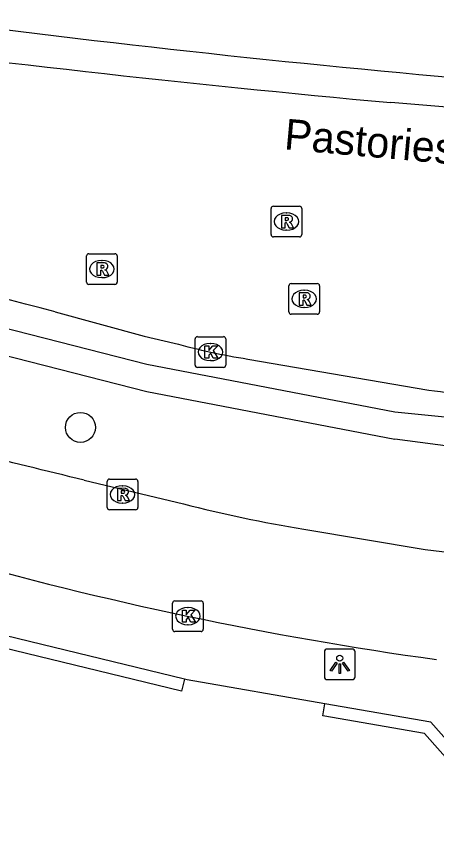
# Model space of a CAD drawing. Extents: x 160861 to 161308, y 384024 to 384878.
# Drawn here: x 161083.27 to 161096.95, y 384841.88 to 384868.78 of the extents above; entities that cross this region are included whole.
import ezdxf

# ---------------------------------------------------------------- set-up
doc = ezdxf.new("R2010")
doc.units = 0
for name, color, linetype in [('IMGEO_Boom', 7, 'Continuous'), ('IMGEO_Haag', 7, 'Continuous'), ('IMGEO_Hek', 7, 'Continuous'), ('IMGEO_Kolk', 7, 'Continuous'), ('IMGEO_Lichtpunt', 7, 'Continuous'), ('IMGEO_Openbare_ruimte_label', 7, 'Continuous'), ('IMGEO_Rijbaan_lokaal_gesloten', 7, 'Continuous'), ('IMGEO_Rijbaan_regionaal_gesloten', 7, 'Continuous'), ('IMGEO_Rioolput', 7, 'Continuous'), ('IMGEO_Voetpad_open', 7, 'Continuous')]:
    doc.layers.add(name, color=color, linetype=linetype)

msp = doc.modelspace()

# ---------------------------------------------------------------- linework, layer by layer
at = {"layer": 'IMGEO_Boom'}
msp.add_circle((161085.352, 384855.4), 0.489, dxfattribs=at)
at = {"layer": 'IMGEO_Haag'}
for points in [[(161088.737, 384847.203), (161088.643, 384846.814), (161078.539, 384849.258), (161075.222, 384849.959), (161068.388, 384851.138)], [(161131.313, 384846.712), (161129.022, 384846.468), (161124.766, 384845.773), (161120.159, 384844.667), (161118.797, 384843.061), (161117.09, 384841.916), (161113.104, 384841.881), (161098.682, 384843.036), (161096.561, 384845.428), (161093.247, 384846.005), (161093.316, 384846.399)]]:
    msp.add_lwpolyline(points, dxfattribs=at)
at = {"layer": 'IMGEO_Hek'}
for points in [[(160981.991, 384864.071), (160981.991, 384864.963), (160990.538, 384865.942), (161000.837, 384866.621), (161011.863, 384866.872), (161023.361, 384866.572), (161034.743, 384865.752), (161045.874, 384864.511), (161070.2, 384861.176), (161078.924, 384859.65), (161087.515, 384857.461), (161095.594, 384855.909)], [(160981.991, 384864.071), (160990.538, 384865.05), (161000.837, 384865.729), (161011.863, 384865.98), (161023.361, 384865.68), (161034.743, 384864.86), (161045.874, 384863.619), (161070.2, 384860.284), (161078.924, 384858.758), (161087.515, 384856.569), (161095.594, 384855.017)], [(161095.594, 384855.909), (161105.396, 384854.928)], [(161100.043, 384854.427), (161095.594, 384855.017)]]:
    msp.add_lwpolyline(points, dxfattribs=at)
at = {"layer": 'IMGEO_Kolk'}
for p, q in [((161089.16, 384858.354), (161090.012, 384858.354)), ((161089.085, 384857.428), (161089.085, 384858.28)), ((161089.573, 384858.134), (161089.598, 384858.134)), ((161090.086, 384858.28), (161090.086, 384857.428)), ((161089.596, 384857.574), (161089.571, 384857.574)), ((161090.012, 384857.354), (161089.16, 384857.354)), ((161088.426, 384849.751), (161089.278, 384849.751)), ((161088.351, 384848.825), (161088.351, 384849.677)), ((161088.839, 384849.531), (161088.864, 384849.531)), ((161089.352, 384849.677), (161089.352, 384848.825)), ((161088.862, 384848.971), (161088.837, 384848.971)), ((161089.278, 384848.751), (161088.426, 384848.751))]:
    msp.add_line(p, q, dxfattribs=at)
for points in [[(161089.16, 384858.354), (161090.012, 384858.354)], [(161089.085, 384857.428), (161089.085, 384858.28)], [(161089.406, 384858.054), (161089.529, 384858.054), (161089.529, 384857.903), (161089.659, 384858.054), (161089.823, 384858.054), (161089.677, 384857.903), (161089.83, 384857.654), (161089.678, 384857.654), (161089.593, 384857.818), (161089.529, 384857.751), (161089.529, 384857.654), (161089.406, 384857.654), (161089.406, 384858.054)], [(161090.086, 384858.28), (161090.086, 384857.428)], [(161090.012, 384857.354), (161089.16, 384857.354)], [(161088.426, 384849.751), (161089.278, 384849.751)], [(161088.351, 384848.825), (161088.351, 384849.677)], [(161088.672, 384849.451), (161088.795, 384849.451), (161088.795, 384849.3), (161088.925, 384849.451), (161089.089, 384849.451), (161088.943, 384849.3), (161089.096, 384849.051), (161088.944, 384849.051), (161088.859, 384849.215), (161088.795, 384849.148), (161088.795, 384849.051), (161088.672, 384849.051), (161088.672, 384849.451)], [(161089.352, 384849.677), (161089.352, 384848.825)], [(161089.278, 384848.751), (161088.426, 384848.751)]]:
    msp.add_lwpolyline(points, dxfattribs=at)
for centre, start, end in [((161089.162, 384858.278), 91.552, 178.448), ((161089.162, 384858.278), 91.552, 178.448), ((161090.01, 384858.278), 1.552, 88.448), ((161090.01, 384858.278), 1.552, 88.448), ((161089.162, 384857.43), 181.552, 268.448), ((161089.162, 384857.43), 181.552, 268.448), ((161090.01, 384857.43), 271.552, 358.448), ((161090.01, 384857.43), 271.552, 358.448), ((161088.428, 384849.675), 91.552, 178.448), ((161088.428, 384849.675), 91.552, 178.448), ((161089.276, 384849.675), 1.552, 88.448), ((161089.276, 384849.675), 1.552, 88.448), ((161088.428, 384848.827), 181.552, 268.448), ((161088.428, 384848.827), 181.552, 268.448), ((161089.276, 384848.827), 271.552, 358.448), ((161089.276, 384848.827), 271.552, 358.448)]:
    msp.add_arc(centre, 0.0765, start, end, dxfattribs=at)
for centre, major_axis, ratio, start_param, end_param in [((161089.572, 384857.854), (-0.387, 0.002), 0.722429, 4.712389, 7.853982), ((161089.597, 384857.854), (-0.39, 0.002), 0.717154, 1.570796, 4.712389), ((161088.838, 384849.251), (-0.387, 0.002), 0.722429, 4.712389, 7.853982), ((161088.863, 384849.251), (-0.39, 0.002), 0.717154, 1.570796, 4.712389)]:
    msp.add_ellipse(centre, major_axis=major_axis, ratio=ratio, start_param=start_param, end_param=end_param, dxfattribs=at)
at = {"layer": 'IMGEO_Lichtpunt'}
for p, q in [((161093.298, 384848.086), (161093.298, 384847.279)), ((161093.298, 384848.086), (161093.298, 384847.279)), ((161094.2, 384848.181), (161093.392, 384848.181)), ((161094.2, 384848.181), (161093.392, 384848.181)), ((161094.294, 384847.279), (161094.294, 384848.086)), ((161094.294, 384847.279), (161094.294, 384848.086)), ((161093.392, 384847.185), (161094.2, 384847.185)), ((161093.392, 384847.185), (161094.2, 384847.185))]:
    msp.add_line(p, q, dxfattribs=at)
for points in [[(161093.672, 384847.75), (161093.711, 384847.722), (161093.523, 384847.46), (161093.485, 384847.487), (161093.672, 384847.75)], [(161093.774, 384847.702), (161093.821, 384847.702), (161093.821, 384847.38), (161093.774, 384847.38), (161093.774, 384847.702)], [(161093.884, 384847.722), (161093.922, 384847.749), (161094.109, 384847.487), (161094.07, 384847.459), (161093.884, 384847.722)]]:
    msp.add_lwpolyline(points, dxfattribs=at)
msp.add_circle((161093.797, 384847.884), 0.0994, dxfattribs=at)
for centre, start, end in [((161093.392, 384848.086), 90, 180), ((161093.392, 384848.086), 90, 180), ((161094.2, 384848.086), 0, 90), ((161094.2, 384848.086), 0, 90), ((161093.392, 384847.279), 180, 270), ((161093.392, 384847.279), 180, 270), ((161094.2, 384847.279), 270, 0), ((161094.2, 384847.279), 270, 360)]:
    msp.add_arc(centre, 0.0946, start, end, dxfattribs=at)
at = {"layer": 'IMGEO_Rijbaan_lokaal_gesloten'}
for points in [[(161085.474, 384853.678), (161088.702, 384852.908)], [(161092.626, 384852.085), (161096.576, 384851.42), (161097.579, 384851.298)]]:
    msp.add_lwpolyline(points, dxfattribs=at)
for centre, radius, start, end in [((160824.463, 383796.83), 1088.602, 76.127183, 76.531378), ((161099.998, 384897), 45.516, 255.6304, 260.6791), ((161113.478, 384966.524), 119.831, 254.19065, 262.07039)]:
    msp.add_arc(centre, radius, start, end, dxfattribs=at)
at = {"layer": 'IMGEO_Rijbaan_regionaal_gesloten'}
for points in [[(161103.416, 384865.317), (161095.457, 384865.978)], [(161084.524, 384859.161), (161087.422, 384858.375), (161088.402, 384858.146)], [(161090.803, 384857.626), (161096.702, 384856.617)]]:
    msp.add_lwpolyline(points, dxfattribs=at)
for centre, radius, start, end in [((161134.125, 385278.867), 413.695, 262.42605, 265.19774), ((161139.404, 385346.014), 482.044, 262.39283, 264.76917), ((161052.796, 384740.74), 122.598, 75.00108, 82.48577), ((161094.191, 384879.075), 21.715, 254.537, 261.0226), ((161105.571, 384916.995), 61.026, 261.64364, 264.46154)]:
    msp.add_arc(centre, radius, start, end, dxfattribs=at)
at = {"layer": 'IMGEO_Rioolput'}
for p, q in [((161091.634, 384862.604), (161092.486, 384862.604)), ((161091.559, 384861.678), (161091.559, 384862.53)), ((161092.047, 384862.384), (161092.072, 384862.384)), ((161092.56, 384862.53), (161092.56, 384861.678)), ((161092.07, 384861.824), (161092.045, 384861.824)), ((161092.486, 384861.604), (161091.634, 384861.604)), ((161085.624, 384861.057), (161086.476, 384861.057)), ((161085.549, 384860.131), (161085.549, 384860.983)), ((161086.037, 384860.837), (161086.062, 384860.837)), ((161086.55, 384860.983), (161086.55, 384860.131)), ((161086.06, 384860.277), (161086.035, 384860.277)), ((161086.476, 384860.057), (161085.624, 384860.057)), ((161092.139, 384859.159), (161092.139, 384860.011)), ((161092.214, 384860.085), (161093.066, 384860.085)), ((161093.14, 384860.011), (161093.14, 384859.159)), ((161092.627, 384859.865), (161092.652, 384859.865)), ((161092.65, 384859.305), (161092.625, 384859.305)), ((161093.066, 384859.085), (161092.214, 384859.085)), ((161086.22, 384852.79), (161086.22, 384853.642)), ((161086.295, 384853.716), (161087.147, 384853.716)), ((161086.708, 384853.496), (161086.733, 384853.496)), ((161087.221, 384853.642), (161087.221, 384852.79)), ((161086.731, 384852.936), (161086.706, 384852.936)), ((161087.147, 384852.716), (161086.295, 384852.716))]:
    msp.add_line(p, q, dxfattribs=at)
for points in [[(161091.634, 384862.604), (161092.486, 384862.604)], [(161091.559, 384861.678), (161091.559, 384862.53)], [(161092.56, 384862.53), (161092.56, 384861.678)], [(161092.148, 384862.302), (161091.896, 384862.304), (161091.896, 384861.904)], [(161091.896, 384861.904), (161092.02, 384861.904), (161092.02, 384862.066), (161092.031, 384862.066)], [(161092.074, 384862.223), (161092.02, 384862.223), (161092.02, 384862.142)], [(161092.02, 384862.142), (161092.072, 384862.142)], [(161092.078, 384862.037), (161092.149, 384861.904), (161092.289, 384861.904), (161092.224, 384862.03)], [(161092.486, 384861.604), (161091.634, 384861.604)], [(161085.624, 384861.057), (161086.476, 384861.057)], [(161085.549, 384860.131), (161085.549, 384860.983)], [(161086.138, 384860.755), (161085.886, 384860.757), (161085.886, 384860.357)], [(161086.55, 384860.983), (161086.55, 384860.131)], [(161085.886, 384860.357), (161086.01, 384860.357), (161086.01, 384860.519), (161086.021, 384860.519)], [(161086.064, 384860.676), (161086.01, 384860.676), (161086.01, 384860.595)], [(161086.01, 384860.595), (161086.062, 384860.595)], [(161086.068, 384860.49), (161086.139, 384860.357), (161086.279, 384860.357), (161086.214, 384860.483)], [(161086.476, 384860.057), (161085.624, 384860.057)], [(161092.139, 384859.159), (161092.139, 384860.011)], [(161092.214, 384860.085), (161093.066, 384860.085)], [(161093.14, 384860.011), (161093.14, 384859.159)], [(161092.728, 384859.783), (161092.476, 384859.785), (161092.476, 384859.385)], [(161092.654, 384859.704), (161092.6, 384859.704), (161092.6, 384859.623)], [(161092.476, 384859.385), (161092.6, 384859.385), (161092.6, 384859.547), (161092.611, 384859.547)], [(161092.6, 384859.623), (161092.652, 384859.623)], [(161092.658, 384859.518), (161092.729, 384859.385), (161092.869, 384859.385), (161092.804, 384859.511)], [(161093.066, 384859.085), (161092.214, 384859.085)], [(161086.22, 384852.79), (161086.22, 384853.642)], [(161086.295, 384853.716), (161087.147, 384853.716)], [(161087.221, 384853.642), (161087.221, 384852.79)], [(161086.809, 384853.414), (161086.557, 384853.416), (161086.557, 384853.016)], [(161086.735, 384853.335), (161086.681, 384853.335), (161086.681, 384853.254)], [(161086.681, 384853.254), (161086.733, 384853.254)], [(161086.557, 384853.016), (161086.681, 384853.016), (161086.681, 384853.178), (161086.692, 384853.178)], [(161086.739, 384853.149), (161086.81, 384853.016), (161086.95, 384853.016), (161086.885, 384853.142)], [(161087.147, 384852.716), (161086.295, 384852.716)]]:
    msp.add_lwpolyline(points, dxfattribs=at)
for centre, radius, start, end in [((161091.636, 384862.528), 0.0765, 91.552, 178.448), ((161091.636, 384862.528), 0.0765, 91.552, 178.448), ((161092.484, 384862.528), 0.0765, 1.552, 88.448), ((161092.484, 384862.528), 0.0765, 1.552, 88.448), ((161092.03, 384862.013), 0.0533, 26.0293, 88.6989), ((161092.056, 384862.331), 0.19, 274.7715, 282.9687), ((161092.08, 384862.127), 0.0964, 77.0061, 93.1865), ((161092.094, 384862.184), 0.0378, 276.6634, 79.6772), ((161092.147, 384862.192), 0.109, 350.3612, 89.416), ((161092.145, 384862.192), 0.112, 277.5842, 350.9817), ((161092.129, 384861.977), 0.108, 29.5134, 73.7905), ((161091.636, 384861.68), 0.0765, 181.552, 268.448), ((161091.636, 384861.68), 0.0765, 181.552, 268.448), ((161092.484, 384861.68), 0.0765, 271.552, 358.448), ((161092.484, 384861.68), 0.0765, 271.552, 358.448), ((161085.626, 384860.981), 0.0765, 91.552, 178.448), ((161085.626, 384860.981), 0.0765, 91.552, 178.448), ((161086.474, 384860.981), 0.0765, 1.552, 88.448), ((161086.474, 384860.981), 0.0765, 1.552, 88.448), ((161086.137, 384860.645), 0.109, 350.3612, 89.416), ((161086.02, 384860.466), 0.0533, 26.0293, 88.6989), ((161086.046, 384860.784), 0.19, 274.7715, 282.9687), ((161086.07, 384860.58), 0.0964, 77.0061, 93.1865), ((161086.084, 384860.637), 0.0378, 276.6634, 79.6772), ((161086.135, 384860.645), 0.112, 277.5842, 350.9817), ((161086.119, 384860.43), 0.108, 29.5134, 73.7905), ((161085.626, 384860.133), 0.0765, 181.552, 268.448), ((161085.626, 384860.133), 0.0765, 181.552, 268.448), ((161086.474, 384860.133), 0.0765, 271.552, 358.448), ((161086.474, 384860.133), 0.0765, 271.552, 358.448), ((161092.216, 384860.009), 0.0765, 91.552, 178.448), ((161092.216, 384860.009), 0.0765, 91.552, 178.448), ((161093.064, 384860.009), 0.0765, 1.552, 88.448), ((161093.064, 384860.009), 0.0765, 1.552, 88.448), ((161092.66, 384859.608), 0.0964, 77.0061, 93.1865), ((161092.674, 384859.665), 0.0378, 276.6634, 79.6772), ((161092.727, 384859.673), 0.109, 350.3612, 89.416), ((161092.725, 384859.673), 0.112, 277.5842, 350.9817), ((161092.61, 384859.494), 0.0533, 26.0293, 88.6989), ((161092.636, 384859.812), 0.19, 274.7715, 282.9687), ((161092.709, 384859.458), 0.108, 29.5134, 73.7905), ((161092.216, 384859.161), 0.0765, 181.552, 268.448), ((161092.216, 384859.161), 0.0765, 181.552, 268.448), ((161093.064, 384859.161), 0.0765, 271.552, 358.448), ((161093.064, 384859.161), 0.0765, 271.552, 358.448), ((161086.297, 384853.64), 0.0765, 91.552, 178.448), ((161086.297, 384853.64), 0.0765, 91.552, 178.448), ((161087.145, 384853.64), 0.0765, 1.552, 88.448), ((161087.145, 384853.64), 0.0765, 1.552, 88.448), ((161086.717, 384853.443), 0.19, 274.7715, 282.9687), ((161086.741, 384853.239), 0.0964, 77.0061, 93.1865), ((161086.755, 384853.296), 0.0378, 276.6634, 79.6772), ((161086.808, 384853.304), 0.109, 350.3612, 89.416), ((161086.806, 384853.304), 0.112, 277.5842, 350.9817), ((161086.79, 384853.089), 0.108, 29.5134, 73.7905), ((161086.691, 384853.125), 0.0533, 26.0293, 88.6989), ((161086.297, 384852.792), 0.0765, 181.552, 268.448), ((161086.297, 384852.792), 0.0765, 181.552, 268.448), ((161087.145, 384852.792), 0.0765, 271.552, 358.448), ((161087.145, 384852.792), 0.0765, 271.552, 358.448)]:
    msp.add_arc(centre, radius, start, end, dxfattribs=at)
for centre, major_axis, ratio, start_param, end_param in [((161092.046, 384862.104), (-0.387, 0.002), 0.722429, 4.712389, 7.853982), ((161092.071, 384862.104), (-0.39, 0.002), 0.717154, 1.570796, 4.712389), ((161086.036, 384860.557), (-0.387, 0.002), 0.722429, 4.712389, 7.853982), ((161086.061, 384860.557), (-0.39, 0.002), 0.717154, 1.570796, 4.712389), ((161092.626, 384859.585), (-0.387, 0.002), 0.722429, 4.712389, 7.853982), ((161092.651, 384859.585), (-0.39, 0.002), 0.717154, 1.570796, 4.712389), ((161086.707, 384853.216), (-0.387, 0.002), 0.722429, 4.712389, 7.853982), ((161086.732, 384853.216), (-0.39, 0.002), 0.717154, 1.570796, 4.712389)]:
    msp.add_ellipse(centre, major_axis=major_axis, ratio=ratio, start_param=start_param, end_param=end_param, dxfattribs=at)
at = {"layer": 'IMGEO_Voetpad_open'}
for points in [[(161088.737, 384847.203), (161078.627, 384849.648), (161075.297, 384850.352), (161068.469, 384851.53)], [(161093.316, 384846.399), (161088.822, 384847.182), (161088.737, 384847.203)], [(161131.371, 384847.12), (161128.969, 384846.865), (161124.687, 384846.165), (161119.939, 384845.025), (161118.528, 384843.362), (161116.967, 384842.315), (161113.118, 384842.281), (161098.874, 384843.422), (161096.767, 384845.798), (161093.316, 384846.399)]]:
    msp.add_lwpolyline(points, dxfattribs=at)

# ---------------------------------------------------------------- texts
at = {"layer": 'IMGEO_Openbare_ruimte_label'}
msp.add_text('Pastoriestraat', height=1, rotation=354.8938, dxfattribs=at).set_placement((161091.964, 384864.46))

doc.saveas('drawing.dxf')
